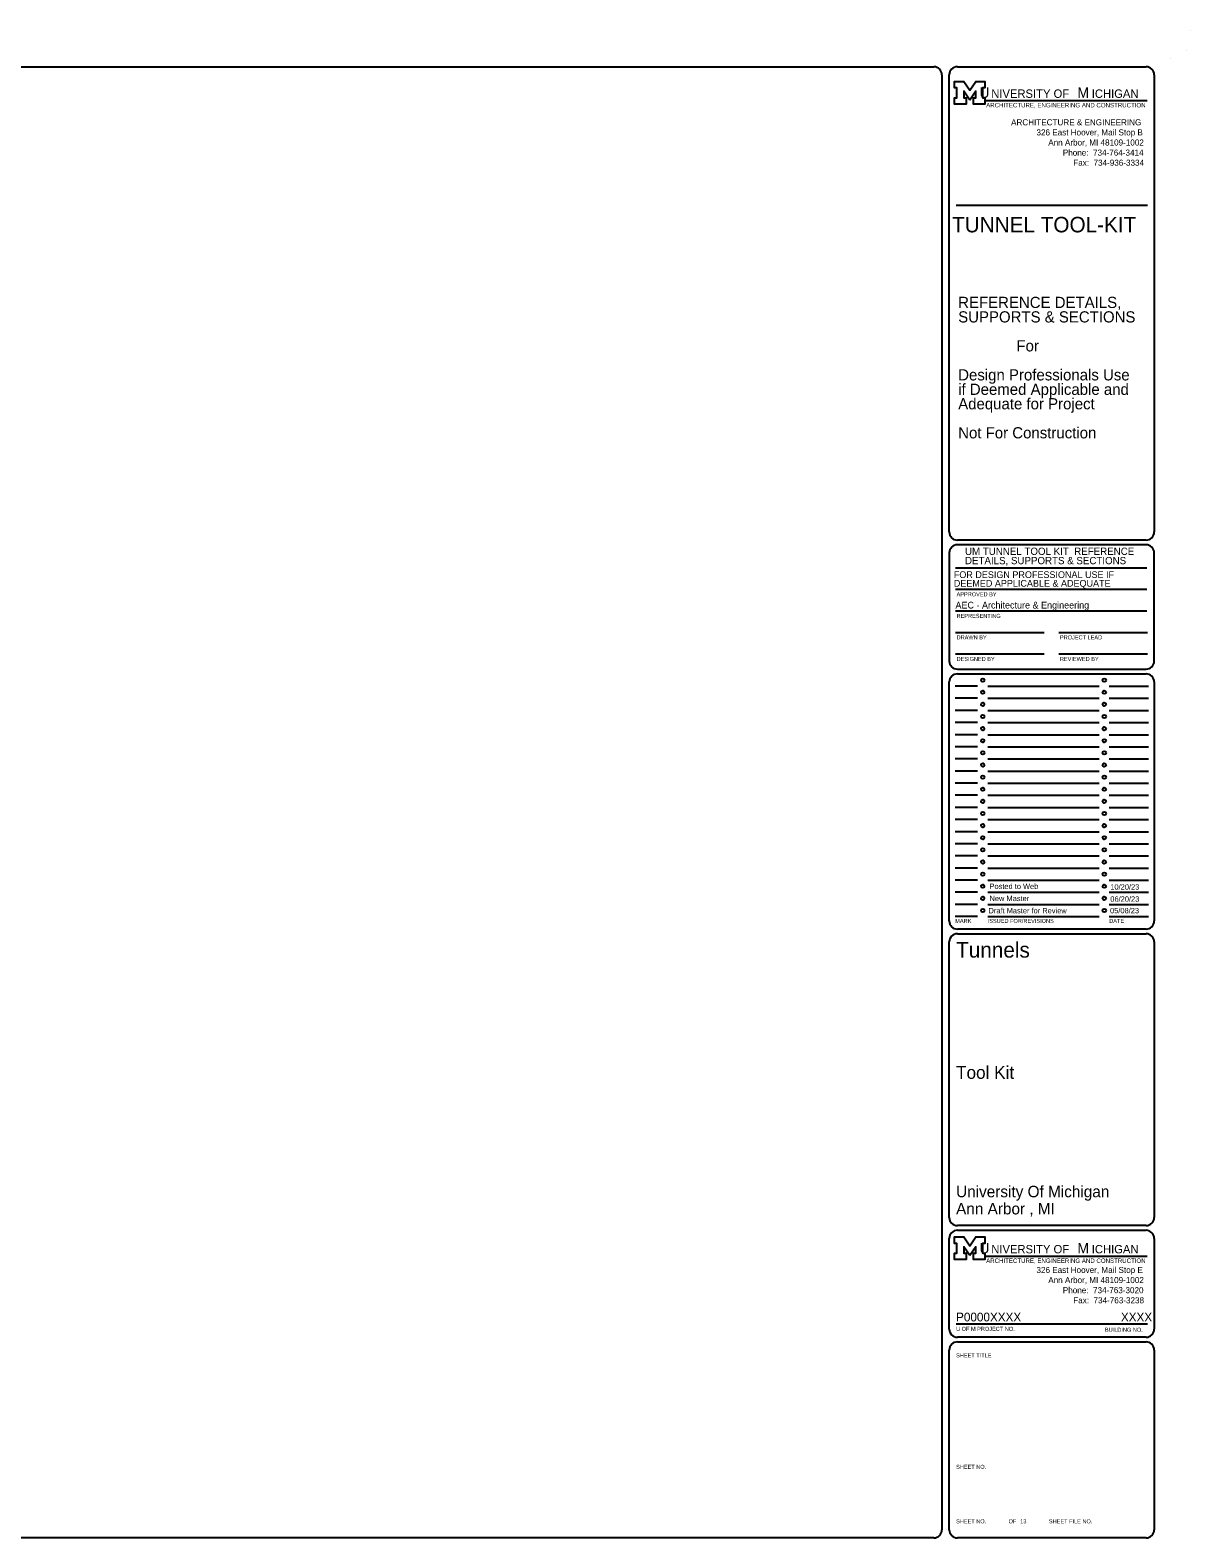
# Model space of a CAD drawing. Extents: x 10001 to 10289, y 9999 to 10191.
# Drawn here: x 10145 to 10288.5, y 10004 to 10190.6 of the extents above; entities that cross this region are included whole.
import ezdxf

# ---------------------------------------------------------------- set-up
doc = ezdxf.new("R2010")
doc.units = 0
for name, color, linetype in [('G-ANNO-LOGO', 7, 'Continuous'), ('G-ANNO-PD', 7, 'Continuous'), ('G-ANNO-PDIJ', 7, 'Continuous'), ('G-ANNO-PDOCE', 7, 'Continuous'), ('G-ANNO-PROJ', 7, 'Continuous'), ('G-ANNO-TEXT', 7, 'Continuous'), ('G-ANNO-TTLB', 7, 'Continuous')]:
    doc.layers.add(name, color=color, linetype=linetype)

msp = doc.modelspace()

# ---------------------------------------------------------------- linework, layer by layer
at = {"layer": 'G-ANNO-LOGO'}
for p, q in [((10263.21, 10181.84), (10283.11, 10181.84)), ((10263.21, 10038.88), (10283.11, 10038.88))]:
    msp.add_line(p, q, dxfattribs=at)
for points in [[(10261.19, 10181.9), (10260.44, 10183), (10260.44, 10182.2), (10260.73, 10182.2), (10260.73, 10181.41), (10259.32, 10181.41), (10259.32, 10182.2), (10259.61, 10182.2), (10259.61, 10183.42), (10259.32, 10183.42), (10259.32, 10184.21), (10260.44, 10184.21), (10261.19, 10183.11), (10261.95, 10184.21), (10263.07, 10184.21), (10263.07, 10183.42), (10262.78, 10183.42), (10262.78, 10182.22), (10262.84, 10182.2), (10263.07, 10182.2), (10263.07, 10181.41), (10261.66, 10181.41), (10261.66, 10182.2), (10261.95, 10182.2), (10261.95, 10183)], [(10261.19, 10038.94), (10260.44, 10040.04), (10260.44, 10039.24), (10260.73, 10039.24), (10260.73, 10038.45), (10259.32, 10038.45), (10259.32, 10039.24), (10259.61, 10039.24), (10259.61, 10040.46), (10259.32, 10040.46), (10259.32, 10041.25), (10260.44, 10041.25), (10261.19, 10040.15), (10261.95, 10041.25), (10263.07, 10041.25), (10263.07, 10040.46), (10262.78, 10040.46), (10262.78, 10039.27), (10262.84, 10039.24), (10263.07, 10039.24), (10263.07, 10038.45), (10261.66, 10038.45), (10261.66, 10039.24), (10261.95, 10039.24), (10261.95, 10040.04)]]:
    msp.add_lwpolyline(points, close=True, dxfattribs=at)
at = {"layer": 'G-ANNO-PD'}
msp.add_line((10288, 10188.09), (10288, 10188.09), dxfattribs=at)
at = {"layer": 'G-ANNO-PDIJ'}
msp.add_line((10286, 10187.02), (10286, 10187.02), dxfattribs=at)
at = {"layer": 'G-ANNO-PDOCE'}
msp.add_line((10288.53, 10190.55), (10288.53, 10190.55), dxfattribs=at)
at = {"layer": 'G-ANNO-TTLB'}
for p, q in [((10013, 10186.02), (10256.75, 10186.02)), ((10257.75, 10185.02), (10257.75, 10005.02)), ((10258.66, 10128.47), (10258.66, 10185.03)), ((10284, 10185.03), (10284, 10128.47)), ((10283.16, 10168.86), (10259.5, 10168.86)), ((10258.66, 10125.88), (10258.66, 10112.5)), ((10284, 10112.5), (10284, 10125.88)), ((10283.08, 10124), (10259.42, 10124)), ((10283.08, 10121.34), (10259.42, 10121.34)), ((10283.08, 10118.67), (10259.42, 10118.67)), ((10270.39, 10116), (10259.42, 10116)), ((10283.17, 10116), (10272.19, 10116)), ((10270.39, 10113.34), (10259.42, 10113.34)), ((10283.17, 10113.34), (10272.19, 10113.34)), ((10258.66, 10080.34), (10258.66, 10109.91)), ((10262.16, 10109.39), (10259.37, 10109.39)), ((10263.41, 10109.39), (10277.19, 10109.39)), ((10278.44, 10109.39), (10283.28, 10109.39)), ((10284, 10109.91), (10284, 10080.34)), ((10262.16, 10107.89), (10259.37, 10107.89)), ((10262.16, 10106.39), (10259.37, 10106.39)), ((10263.41, 10107.89), (10277.19, 10107.89)), ((10263.41, 10106.39), (10277.19, 10106.39)), ((10278.44, 10107.89), (10283.28, 10107.89)), ((10278.44, 10106.39), (10283.28, 10106.39)), ((10262.16, 10104.89), (10259.37, 10104.89)), ((10263.41, 10104.89), (10277.19, 10104.89)), ((10278.44, 10104.89), (10283.28, 10104.89)), ((10262.16, 10103.39), (10259.37, 10103.39)), ((10263.41, 10103.39), (10277.19, 10103.39)), ((10278.44, 10103.39), (10283.28, 10103.39)), ((10262.16, 10101.89), (10259.37, 10101.89)), ((10263.41, 10101.89), (10277.19, 10101.89)), ((10278.44, 10101.89), (10283.28, 10101.89)), ((10262.16, 10100.39), (10259.37, 10100.39)), ((10262.16, 10098.89), (10259.37, 10098.89)), ((10263.41, 10100.39), (10277.19, 10100.39)), ((10263.41, 10098.89), (10277.19, 10098.89)), ((10278.44, 10100.39), (10283.28, 10100.39)), ((10278.44, 10098.89), (10283.28, 10098.89)), ((10262.16, 10097.39), (10259.37, 10097.39)), ((10263.41, 10097.39), (10277.19, 10097.39)), ((10278.44, 10097.39), (10283.28, 10097.39)), ((10262.16, 10095.89), (10259.37, 10095.89)), ((10263.41, 10095.89), (10277.19, 10095.89)), ((10278.44, 10095.89), (10283.28, 10095.89)), ((10262.16, 10094.39), (10259.37, 10094.39)), ((10263.41, 10094.39), (10277.19, 10094.39)), ((10278.44, 10094.39), (10283.28, 10094.39)), ((10262.16, 10092.89), (10259.37, 10092.89)), ((10262.16, 10091.39), (10259.37, 10091.39)), ((10263.41, 10092.89), (10277.19, 10092.89)), ((10263.41, 10091.39), (10277.19, 10091.39)), ((10278.44, 10092.89), (10283.28, 10092.89)), ((10278.44, 10091.39), (10283.28, 10091.39)), ((10262.16, 10089.89), (10259.37, 10089.89)), ((10263.41, 10089.89), (10277.19, 10089.89)), ((10278.44, 10089.89), (10283.28, 10089.89)), ((10262.16, 10088.39), (10259.37, 10088.39)), ((10263.41, 10088.39), (10277.19, 10088.39)), ((10278.44, 10088.39), (10283.28, 10088.39)), ((10262.16, 10086.89), (10259.37, 10086.89)), ((10263.41, 10086.89), (10277.19, 10086.89)), ((10278.44, 10086.89), (10283.28, 10086.89)), ((10262.16, 10085.39), (10259.37, 10085.39)), ((10263.41, 10085.39), (10277.19, 10085.39)), ((10278.44, 10085.39), (10283.28, 10085.39)), ((10262.16, 10083.89), (10259.37, 10083.89)), ((10262.16, 10082.39), (10259.37, 10082.39)), ((10263.41, 10083.89), (10277.19, 10083.89)), ((10263.41, 10082.39), (10277.19, 10082.39)), ((10278.44, 10083.89), (10283.28, 10083.89)), ((10278.44, 10082.39), (10283.28, 10082.39)), ((10262.16, 10080.89), (10259.37, 10080.89)), ((10263.41, 10080.89), (10277.19, 10080.89)), ((10278.44, 10080.89), (10283.28, 10080.89)), ((10258.66, 10043.65), (10258.66, 10077.76)), ((10284, 10077.76), (10284, 10043.65)), ((10258.66, 10029.84), (10258.66, 10041.07)), ((10284, 10041.07), (10284, 10029.84)), ((10283.16, 10030.46), (10259.5, 10030.46)), ((10258.66, 10005.02), (10258.66, 10027.26)), ((10284, 10027.26), (10284, 10005.02)), ((10256.75, 10004.02), (10013, 10004.02))]:
    msp.add_line(p, q, dxfattribs=at)
for points in [[(10259.66, 10186.03), (10283, 10186.03)], [(10283, 10127.47), (10259.66, 10127.47)], [(10283, 10126.88), (10259.66, 10126.88)], [(10259.66, 10111.5), (10283, 10111.5)], [(10259.66, 10110.91), (10283, 10110.91)], [(10283, 10079.34), (10259.66, 10079.34)], [(10259.66, 10078.76), (10283, 10078.76)], [(10283, 10042.65), (10259.66, 10042.65)], [(10259.66, 10042.07), (10283, 10042.07)], [(10283, 10028.84), (10259.66, 10028.84)], [(10259.66, 10028.26), (10283, 10028.26)], [(10283, 10004.02), (10259.66, 10004.02)]]:
    msp.add_lwpolyline(points, dxfattribs=at)
for centre in [(10262.8, 10110.14), (10277.83, 10110.14), (10262.8, 10108.64), (10277.83, 10108.64), (10262.8, 10107.14), (10277.83, 10107.14), (10262.8, 10105.64), (10277.83, 10105.64), (10262.8, 10104.14), (10262.8, 10102.64), (10277.83, 10104.14), (10277.83, 10102.64), (10262.8, 10101.14), (10277.83, 10101.14), (10262.8, 10099.64), (10277.83, 10099.64), (10262.8, 10098.14), (10277.83, 10098.14), (10262.8, 10096.64), (10262.8, 10095.14), (10277.83, 10096.64), (10277.83, 10095.14), (10262.8, 10093.64), (10277.83, 10093.64), (10262.8, 10092.14), (10277.83, 10092.14), (10262.8, 10090.64), (10277.83, 10090.64), (10262.8, 10089.14), (10262.8, 10087.64), (10277.83, 10089.14), (10277.83, 10087.64), (10262.8, 10086.14), (10277.83, 10086.14), (10262.8, 10084.64), (10277.83, 10084.64), (10262.8, 10083.14), (10277.83, 10083.14), (10262.8, 10081.64), (10277.83, 10081.64)]:
    msp.add_circle(centre, 0.214, dxfattribs=at)
for centre, start, end in [((10256.75, 10185.02), 0, 90.0001), ((10259.66, 10185.03), 90, 180), ((10283, 10185.03), 0, 90), ((10259.66, 10128.47), 180, 270), ((10259.66, 10125.88), 90, 180), ((10283, 10128.47), 270, 0), ((10283, 10125.88), 0, 90), ((10259.66, 10112.5), 180, 270), ((10283, 10112.5), 270, 0), ((10259.66, 10109.91), 90, 180), ((10283, 10109.91), 0, 90), ((10259.66, 10080.34), 180, 270), ((10283, 10080.34), 270, 0), ((10259.66, 10077.76), 90, 180), ((10283, 10077.76), 0, 90), ((10259.66, 10043.65), 180, 270), ((10283, 10043.65), 270, 0), ((10259.66, 10041.07), 90, 180), ((10283, 10041.07), 0, 90), ((10259.66, 10029.84), 180, 270), ((10283, 10029.84), 270, 0), ((10259.66, 10027.26), 90, 180), ((10283, 10027.26), 0, 90), ((10256.75, 10005.02), 270.0001, 0), ((10259.66, 10005.02), 180, 270), ((10283, 10005.02), 270, 0)]:
    msp.add_arc(centre, 1, start, end, dxfattribs=at)

# ---------------------------------------------------------------- texts
at = {"layer": 'G-ANNO-LOGO'}
for s, height, p in [('U', 1.28, (10262.39, 10182.18)), ('NIVERSITY OF', 1.0368, (10263.85, 10182.18)), ('M', 1.28, (10274.51, 10182.18)), ('ICHIGAN', 1.037, (10276.28, 10182.18)), ('ARCHITECTURE, ENGINEERING AND CONSTRUCTION', 0.5469, (10263.22, 10181)), ('ARCHITECTURE & ENGINEERING', 0.75, (10266.3, 10178.78)), ('326 East Hoover, Mail Stop B', 0.75, (10269.44, 10177.53)), ('Ann Arbor, MI 48109-1002', 0.75, (10270.9, 10176.28)), ('Phone:  734-764-3414', 0.75, (10272.7, 10175.03)), ('Fax:  734-936-3334', 0.75, (10273.99, 10173.78)), ('U', 1.28, (10262.39, 10039.22)), ('NIVERSITY OF', 1.0368, (10263.85, 10039.22)), ('M', 1.28, (10274.51, 10039.22)), ('ICHIGAN', 1.037, (10276.28, 10039.22)), ('ARCHITECTURE, ENGINEERING AND CONSTRUCTION', 0.5469, (10263.22, 10038.04)), ('326 East Hoover, Mail Stop E', 0.75, (10269.44, 10036.79)), ('Ann Arbor, MI 48109-1002', 0.75, (10270.9, 10035.54)), ('Phone:  734-763-3020', 0.75, (10272.7, 10034.29)), ('Fax:  734-763-3238', 0.75, (10273.99, 10033.04)), ('Fax:  734-763-3238', 0.75, (10273.99, 10033.04))]:
    msp.add_text(s, height=height, dxfattribs=at).set_placement(p)
at = {"layer": 'G-ANNO-PROJ'}
for s, height, p in [('TUNNEL TOOL-KIT', 1.9167, (10259, 10165.54)), ('UM TUNNEL TOOL KIT  REFERENCE', 0.9, (10260.6, 10125.63)), ('DETAILS, SUPPORTS & SECTIONS', 0.9, (10260.6, 10124.48)), ('FOR DESIGN PROFESSIONAL USE IF ', 0.8333, (10259.22, 10122.77)), ('DEEMED APPLICABLE & ADEQUATE ', 0.8333, (10259.22, 10121.7)), ('AEC - Architecture & Engineering', 0.8333, (10259.42, 10119)), ('Posted to Web        ', 0.6667, (10263.63, 10084.3)), ('10/20/23', 0.667, (10278.57, 10084.22)), ('New Master           ', 0.6667, (10263.63, 10082.8)), ('06/20/23', 0.667, (10278.57, 10082.72)), ('Draft Master for Review       ', 0.6667, (10263.51, 10081.29)), ('05/08/23', 0.667, (10278.54, 10081.29)), ('Tunnels', 1.917, (10259.5, 10075.81)), ('Tool Kit', 1.583, (10259.5, 10060.81)), ('University Of Michigan', 1.4167, (10259.5, 10046.16)), ('Ann Arbor , MI', 1.4167, (10259.5, 10044.04)), ('P0000XXXX', 1.083, (10259.5, 10030.8)), ('XXXX', 1.083, (10279.88, 10030.8)), ('SHEET NO.', 0.5, (10259.5, 10005.82)), ('OF', 0.5, (10265.99, 10005.82)), ('13', 0.5, (10267.43, 10005.82))]:
    msp.add_text(s, height=height, dxfattribs=at).set_placement(p)
at = {"layer": 'G-ANNO-TEXT'}
for s, p in [('REFERENCE DETAILS,', (10259.76, 10156.18)), ('SUPPORTS & SECTIONS', (10259.76, 10154.39)), ('              For ', (10259.76, 10150.81)), ('Design Professionals Use', (10259.76, 10147.22)), ('if Deemed Applicable and', (10259.76, 10145.43)), ('Adequate for Project ', (10259.76, 10143.64)), ('Not For Construction ', (10259.76, 10140.05))]:
    msp.add_text(s, height=1.3848, dxfattribs=at).set_placement(p)
at = {"layer": 'G-ANNO-TTLB'}
for s, p in [('APPROVED BY', (10259.56, 10120.51)), ('REPRESENTING', (10259.56, 10117.84)), ('DRAWN BY', (10259.56, 10115.18)), ('PROJECT LEAD', (10272.34, 10115.18)), ('DESIGNED BY', (10259.56, 10112.51)), ('REVIEWED BY', (10272.34, 10112.51)), ('MARK', (10259.4, 10080.1)), ('ISSUED FOR/REVISIONS', (10263.41, 10080.1)), ('DATE', (10278.44, 10080.1)), ('U OF M PROJECT NO.', (10259.5, 10029.63)), ('BUILDING NO.', (10277.91, 10029.52)), ('SHEET TITLE', (10259.5, 10026.35)), ('SHEET NO.', (10259.5, 10012.56)), ('SHEET FILE NO.', (10270.98, 10005.82))]:
    msp.add_text(s, height=0.5, dxfattribs=at).set_placement(p)

doc.saveas('drawing.dxf')
